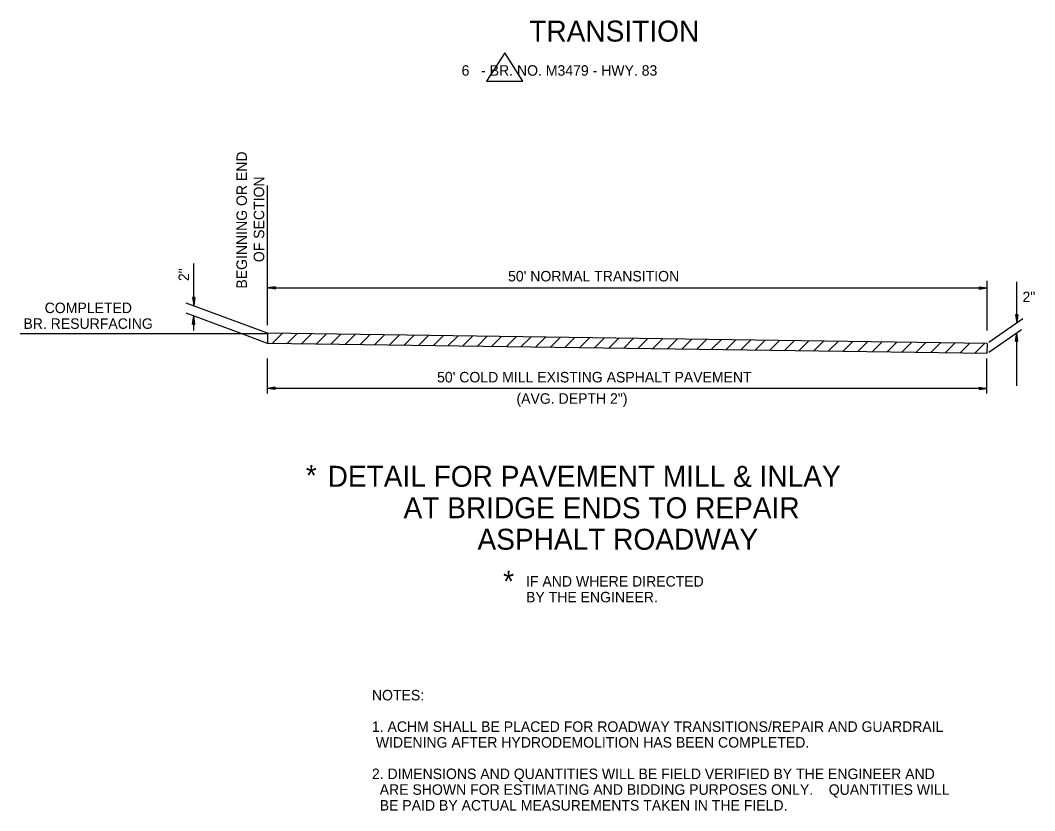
# Model space of a CAD drawing. Extents: x 1929624 to 1935547, y 596315 to 605721.
# Drawn here: x 1933125 to 1933705, y 602270 to 602722 of the extents above; entities that cross this region are included whole.
import ezdxf

# ---------------------------------------------------------------- set-up
doc = ezdxf.new("R2010")
doc.units = 0
for name, color, linetype in [('Default', 7, 'Continuous'), ('R_Border', 7, 'Continuous'), ('R_Draft', 7, 'Continuous')]:
    doc.layers.add(name, color=color, linetype=linetype)

msp = doc.modelspace()

# ---------------------------------------------------------------- linework, layer by layer
at = {"layer": 'Default'}
for p, q in [((1933266.14, 602547.16), (1933266.14, 602627.02)), ((1933223.94, 602558.5), (1933223.94, 602582.49)), ((1933677.69, 602544.07), (1933677.69, 602572.48)), ((1933694.56, 602548.5), (1933694.56, 602572.04)), ((1933270.8, 602569.16), (1933266.13, 602568.49)), ((1933266.13, 602568.49), (1933677.69, 602568.49)), ((1933270.8, 602567.83), (1933266.13, 602568.49)), ((1933270.8, 602568.94), (1933266.81, 602568.49)), ((1933270.8, 602567.83), (1933266.81, 602568.49)), ((1933270.8, 602568.94), (1933267.7, 602568.49)), ((1933270.8, 602568.05), (1933267.7, 602568.49)), ((1933270.8, 602568.72), (1933268.59, 602568.49)), ((1933270.8, 602568.05), (1933268.59, 602568.49)), ((1933270.8, 602568.72), (1933269.25, 602568.49)), ((1933270.8, 602568.28), (1933269.25, 602568.49)), ((1933270.8, 602568.49), (1933270.14, 602568.49)), ((1933270.8, 602568.28), (1933270.14, 602568.49)), ((1933270.8, 602567.83), (1933270.8, 602569.16)), ((1933673.02, 602569.16), (1933677.69, 602568.49)), ((1933673.02, 602569.16), (1933673.02, 602567.83)), ((1933673.02, 602568.94), (1933676.14, 602568.49)), ((1933673.02, 602568.94), (1933676.79, 602568.49)), ((1933673.02, 602568.72), (1933674.57, 602568.49)), ((1933673.02, 602568.72), (1933675.25, 602568.49)), ((1933673.02, 602567.83), (1933677.69, 602568.49)), ((1933673.02, 602568.28), (1933674.57, 602568.49)), ((1933673.02, 602568.05), (1933676.14, 602568.49)), ((1933673.02, 602567.83), (1933676.79, 602568.49)), ((1933673.02, 602568.05), (1933675.25, 602568.49)), ((1933673.02, 602568.28), (1933673.69, 602568.49)), ((1933673.02, 602568.49), (1933673.69, 602568.49)), ((1933266.13, 602542.51), (1933219.73, 602559.83)), ((1933223.27, 602562.95), (1933223.94, 602558.5)), ((1933223.27, 602562.95), (1933223.94, 602559.17)), ((1933224.61, 602562.95), (1933223.27, 602562.95)), ((1933223.5, 602562.95), (1933223.94, 602560.06)), ((1933223.5, 602562.95), (1933223.94, 602560.72)), ((1933223.72, 602562.95), (1933223.94, 602561.61)), ((1933223.72, 602562.95), (1933223.94, 602562.27)), ((1933224.61, 602562.95), (1933223.94, 602558.5)), ((1933224.16, 602562.95), (1933223.94, 602561.61)), ((1933224.39, 602562.95), (1933223.94, 602560.06)), ((1933224.39, 602562.95), (1933223.94, 602559.17)), ((1933224.16, 602562.95), (1933223.94, 602560.72)), ((1933223.94, 602562.95), (1933223.94, 602562.27)), ((1933250.59, 602542.54), (1933219.73, 602554.06)), ((1933693.9, 602553.16), (1933694.56, 602548.5)), ((1933695.23, 602553.16), (1933693.9, 602553.16)), ((1933694.13, 602553.16), (1933694.56, 602550.06)), ((1933694.13, 602553.16), (1933694.56, 602549.39)), ((1933694.33, 602553.16), (1933694.56, 602551.62)), ((1933694.33, 602553.16), (1933694.56, 602550.95)), ((1933695.23, 602553.16), (1933694.56, 602548.5)), ((1933694.78, 602553.16), (1933694.56, 602551.62)), ((1933695.01, 602553.16), (1933694.56, 602550.06)), ((1933695.23, 602553.16), (1933694.56, 602549.39)), ((1933695.01, 602553.16), (1933694.56, 602550.95)), ((1933694.56, 602553.16), (1933694.56, 602552.5)), ((1933694.78, 602553.16), (1933694.56, 602552.5)), ((1933223.27, 602547.83), (1933223.94, 602552.5)), ((1933223.27, 602547.83), (1933223.94, 602551.83)), ((1933223.27, 602547.83), (1933224.61, 602547.83)), ((1933223.5, 602547.83), (1933223.94, 602550.95)), ((1933223.5, 602547.83), (1933223.94, 602550.29)), ((1933223.72, 602547.83), (1933223.94, 602549.39)), ((1933223.72, 602547.83), (1933223.94, 602548.5)), ((1933224.61, 602547.83), (1933223.94, 602552.5)), ((1933223.94, 602544.07), (1933223.94, 602552.5)), ((1933224.39, 602547.83), (1933223.94, 602551.83)), ((1933224.39, 602547.83), (1933223.94, 602550.95)), ((1933224.16, 602547.83), (1933223.94, 602550.29)), ((1933224.16, 602547.83), (1933223.94, 602549.39)), ((1933223.94, 602547.83), (1933223.94, 602548.5)), ((1933678.68, 602537.43), (1933698.11, 602550.95)), ((1933124.79, 602542.5), (1933266.14, 602542.5)), ((1933266.13, 602536.74), (1933250.59, 602542.54)), ((1933677.69, 602536.74), (1933266.13, 602542.51)), ((1933268.82, 602536.7), (1933274.5, 602542.39)), ((1933277.18, 602536.58), (1933282.87, 602542.27)), ((1933285.55, 602536.47), (1933291.24, 602542.15)), ((1933293.92, 602536.35), (1933299.61, 602542.04)), ((1933302.29, 602536.23), (1933307.97, 602541.92)), ((1933310.65, 602536.11), (1933316.34, 602541.8)), ((1933319.02, 602535.99), (1933324.71, 602541.68)), ((1933327.39, 602535.88), (1933333.08, 602541.57)), ((1933335.76, 602535.76), (1933341.45, 602541.45)), ((1933678.65, 602531.78), (1933697.23, 602544.72)), ((1933693.9, 602538.07), (1933694.56, 602542.74)), ((1933694.13, 602538.07), (1933694.56, 602542.07)), ((1933694.56, 602512.53), (1933694.56, 602542.74)), ((1933695.23, 602538.07), (1933694.56, 602542.74)), ((1933695.23, 602538.07), (1933694.56, 602542.07)), ((1933677.46, 602530.95), (1933266.13, 602536.74)), ((1933344.12, 602535.64), (1933349.81, 602541.33)), ((1933352.49, 602535.52), (1933358.18, 602541.22)), ((1933360.86, 602535.41), (1933366.55, 602541.1)), ((1933369.23, 602535.29), (1933374.92, 602540.98)), ((1933377.59, 602535.17), (1933383.29, 602540.86)), ((1933385.96, 602535.05), (1933391.65, 602540.75)), ((1933394.33, 602534.94), (1933400.02, 602540.63)), ((1933402.7, 602534.82), (1933408.39, 602540.51)), ((1933411.06, 602534.7), (1933416.76, 602540.39)), ((1933419.43, 602534.58), (1933425.13, 602540.28)), ((1933427.8, 602534.46), (1933433.49, 602540.16)), ((1933436.17, 602534.35), (1933441.86, 602540.04)), ((1933444.53, 602534.23), (1933450.23, 602539.93)), ((1933452.9, 602534.11), (1933458.6, 602539.81)), ((1933461.27, 602533.99), (1933466.97, 602539.69)), ((1933469.64, 602533.88), (1933475.33, 602539.57)), ((1933478, 602533.76), (1933483.7, 602539.46)), ((1933486.37, 602533.64), (1933492.07, 602539.34)), ((1933494.74, 602533.52), (1933500.44, 602539.22)), ((1933503.11, 602533.4), (1933508.81, 602539.1)), ((1933511.47, 602533.29), (1933517.17, 602538.99)), ((1933519.84, 602533.17), (1933525.54, 602538.87)), ((1933528.21, 602533.05), (1933533.91, 602538.75)), ((1933536.58, 602532.93), (1933542.28, 602538.64)), ((1933544.94, 602532.82), (1933550.65, 602538.52)), ((1933553.31, 602532.7), (1933559.02, 602538.4)), ((1933561.68, 602532.58), (1933567.38, 602538.28)), ((1933570.05, 602532.46), (1933575.75, 602538.17)), ((1933578.41, 602532.35), (1933584.12, 602538.05)), ((1933586.78, 602532.23), (1933592.49, 602537.93)), ((1933595.15, 602532.11), (1933600.86, 602537.82)), ((1933603.52, 602531.99), (1933609.22, 602537.7)), ((1933611.89, 602531.87), (1933617.59, 602537.58)), ((1933620.25, 602531.76), (1933625.96, 602537.46)), ((1933628.62, 602531.64), (1933634.33, 602537.35)), ((1933636.99, 602531.52), (1933642.7, 602537.23)), ((1933645.36, 602531.4), (1933651.06, 602537.11)), ((1933653.72, 602531.29), (1933659.43, 602536.99)), ((1933662.09, 602531.17), (1933667.8, 602536.88)), ((1933670.46, 602531.05), (1933676.17, 602536.76)), ((1933677.69, 602536.74), (1933677.46, 602530.95)), ((1933693.9, 602538.07), (1933695.23, 602538.07)), ((1933694.13, 602538.07), (1933694.56, 602541.17)), ((1933694.33, 602538.07), (1933694.56, 602540.51)), ((1933694.33, 602538.07), (1933694.56, 602539.61)), ((1933695.01, 602538.07), (1933694.56, 602541.17)), ((1933695.01, 602538.07), (1933694.56, 602540.51)), ((1933694.78, 602538.07), (1933694.56, 602539.61)), ((1933694.78, 602538.07), (1933694.56, 602538.96)), ((1933694.56, 602538.07), (1933694.56, 602538.96)), ((1933266.13, 602508.08), (1933266.13, 602528.06)), ((1933677.46, 602508.08), (1933677.46, 602528.06)), ((1933270.6, 602511.63), (1933266.13, 602510.98)), ((1933270.6, 602511.63), (1933266.13, 602510.98)), ((1933677.46, 602510.98), (1933266.13, 602510.98)), ((1933270.6, 602510.3), (1933266.13, 602510.98)), ((1933270.6, 602510.3), (1933266.13, 602510.98)), ((1933270.6, 602511.63), (1933266.81, 602510.98)), ((1933270.6, 602511.63), (1933266.81, 602510.98)), ((1933270.6, 602510.53), (1933266.81, 602510.98)), ((1933270.6, 602510.53), (1933266.81, 602510.98)), ((1933270.6, 602511.42), (1933267.7, 602510.98)), ((1933270.6, 602511.42), (1933267.7, 602510.98)), ((1933270.6, 602510.53), (1933267.7, 602510.98)), ((1933270.6, 602510.53), (1933267.7, 602510.98)), ((1933270.6, 602511.42), (1933268.36, 602510.98)), ((1933270.6, 602511.42), (1933268.36, 602510.98)), ((1933270.6, 602510.75), (1933268.36, 602510.98)), ((1933270.6, 602510.75), (1933268.36, 602510.98)), ((1933270.6, 602511.18), (1933269.25, 602510.98)), ((1933270.6, 602511.18), (1933269.25, 602510.98)), ((1933270.6, 602510.75), (1933269.25, 602510.98)), ((1933270.6, 602510.75), (1933269.25, 602510.98)), ((1933270.6, 602511.18), (1933269.92, 602510.98)), ((1933270.6, 602511.18), (1933269.92, 602510.98)), ((1933270.6, 602510.98), (1933269.92, 602510.98)), ((1933270.6, 602510.98), (1933269.92, 602510.98)), ((1933270.6, 602510.3), (1933270.6, 602511.63)), ((1933270.6, 602510.3), (1933270.6, 602511.63)), ((1933673.02, 602511.63), (1933677.46, 602510.98)), ((1933673.02, 602511.63), (1933676.79, 602510.98)), ((1933673.02, 602511.63), (1933673.02, 602510.3)), ((1933673.02, 602511.42), (1933675.91, 602510.98)), ((1933673.02, 602511.42), (1933675.25, 602510.98)), ((1933673.02, 602511.18), (1933674.36, 602510.98)), ((1933673.02, 602511.18), (1933673.69, 602510.98)), ((1933673.02, 602510.3), (1933677.46, 602510.98)), ((1933673.02, 602510.75), (1933674.36, 602510.98)), ((1933673.02, 602510.53), (1933675.91, 602510.98)), ((1933673.02, 602510.53), (1933676.79, 602510.98)), ((1933673.02, 602510.75), (1933675.25, 602510.98)), ((1933673.02, 602510.98), (1933673.69, 602510.98))]:
    msp.add_line(p, q, dxfattribs=at)
at = {"layer": 'R_Border'}
for p, q in [((1933401.81, 602702.92), (1933391.46, 602686.7)), ((1933412.16, 602686.7), (1933401.81, 602702.92)), ((1933391.46, 602686.7), (1933412.16, 602686.7)), ((1933266.13, 602542.51), (1933266.13, 602536.74))]:
    msp.add_line(p, q, dxfattribs=at)

# ---------------------------------------------------------------- texts
at = {"layer": 'Default'}
for s, height, rotation, p in [('TRANSITION', 12, 360, (1933415.84, 602709.34)), ('BEGINNING OR END', 6, 90, (1933254.4, 602568.06)), ('OF SECTION', 6, 90, (1933264.26, 602583.18)), ('2"', 6, 90, (1933221.28, 602572.38)), ("50' NORMAL TRANSITION", 6, 360, (1933403.73, 602572.19)), ('2"', 6, 360, (1933697.9, 602560.33)), ('COMPLETED', 6, 360, (1933138.72, 602554.07)), ('BR. RESURFACING', 6, 360, (1933126.57, 602545.07)), ("50' COLD MILL EXISTING ASPHALT PAVEMENT", 6, 360, (1933363.13, 602514.44)), ('(AVG. DEPTH 2")', 6, 360, (1933408.53, 602502.23))]:
    msp.add_text(s, height=height, rotation=rotation, dxfattribs=at).set_placement(p)
at = {"layer": 'R_Border'}
for s, height, p in [('*', 12, (1933288.08, 602455.26)), ('DETAIL FOR PAVEMENT MILL & INLAY', 12, (1933300.54, 602454.74)), ('AT BRIDGE ENDS TO REPAIR', 12, (1933343.96, 602436.74)), ('ASPHALT ROADWAY', 12, (1933386.24, 602418.74)), ('*', 12, (1933400.9, 602394.75)), ('IF AND WHERE DIRECTED', 6, (1933414, 602397.68)), ('BY THE ENGINEER.', 6, (1933414, 602388.68)), ('NOTES:', 6, (1933325.86, 602332.6)), ('1. ACHM SHALL BE PLACED FOR ROADWAY TRANSITIONS/REPAIR AND GUARDRAIL', 6, (1933325.86, 602314.6)), (' WIDENING AFTER HYDRODEMOLITION HAS BEEN COMPLETED.', 6, (1933325.86, 602305.6)), ('2. DIMENSIONS AND QUANTITIES WILL BE FIELD VERIFIED BY THE ENGINEER AND ', 6, (1933325.86, 602287.6)), ('  ARE SHOWN FOR ESTIMATING AND BIDDING PURPOSES ONLY.    QUANTITIES WILL', 6, (1933325.86, 602278.6)), ('  BE PAID BY ACTUAL MEASUREMENTS TAKEN IN THE FIELD. ', 6, (1933325.86, 602269.6))]:
    msp.add_text(s, height=height, rotation=360, dxfattribs=at).set_placement(p)
at = {"layer": 'R_Draft'}
msp.add_text('      6   - BR. NO. M3479 - HWY. 83', height=6, dxfattribs=at).set_placement((1933363.78, 602689.83))

doc.saveas('drawing.dxf')
